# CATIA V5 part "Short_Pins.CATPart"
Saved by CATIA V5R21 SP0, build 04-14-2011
Part number: Short_Pins
Bounding box of the stored display mesh (mm): x -25 to 25, y 70.003 to 89.997, z -19.997 to -0.003
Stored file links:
  C:\Users\swlee\Desktop\Short_Pins.CATPart
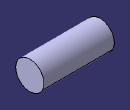
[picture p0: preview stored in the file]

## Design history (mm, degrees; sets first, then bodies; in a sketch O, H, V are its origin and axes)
AxisSystem1: origin (0, 0, 0), X (1, 0, 0), Y (0, 1, 0), Z (0, 0, 1)
Body1 (main body)
  DatumSurface1
  DatumCurve1
  Sketch1 on face of DatumSurface1, origin (25, 0, 0), H (0, -1, 0), V (0, 0, 1)
    circle A1 centre (-80, -10) radius 10
    fix: A1
  Pad1: profile Sketch1, direction (-1, 0, 0), length 50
